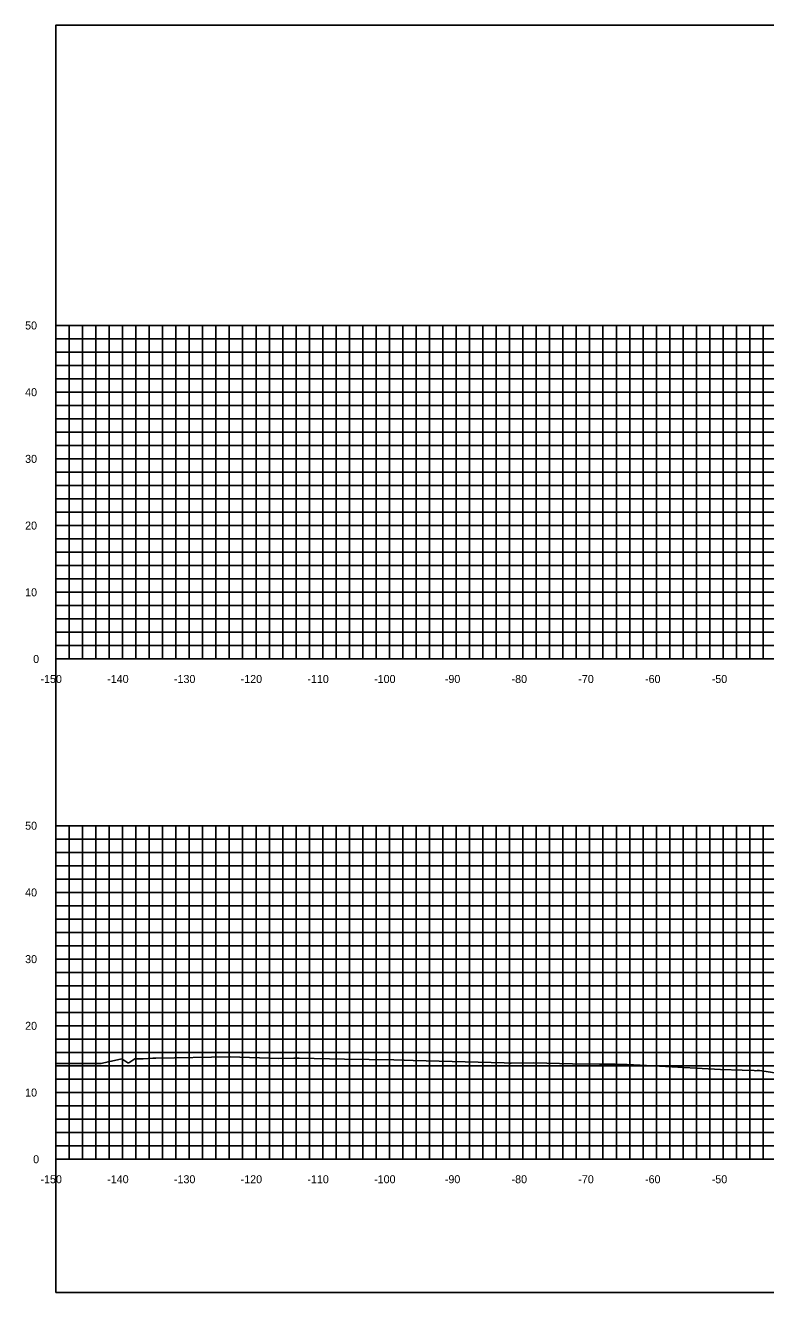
# Model space of a CAD drawing. Extents: x 1797714 to 1804825, y 249015 to 250269.
# Drawn here: x 1802449.6 to 1802560.5, y 249628.2 to 249818.2 of the extents above; entities that cross this region are included whole.
import ezdxf

# ---------------------------------------------------------------- set-up
doc = ezdxf.new("R2010")
doc.units = 0
for name, color, linetype in [('10', 7, 'Continuous'), ('31', 7, 'Continuous'), ('60', 7, 'Continuous'), ('Level 62', 7, 'Continuous'), ('M-ROADS', 7, 'Continuous')]:
    doc.layers.add(name, color=color, linetype=linetype)

msp = doc.modelspace()

# ---------------------------------------------------------------- linework, layer by layer
msp.add_lwpolyline([(1802454.16, 249628.17), (1802754.16, 249628.17), (1802754.16, 249818.17), (1802454.16, 249818.17)], close=True)
at = {"layer": '60'}
for p, q in [((1802454.1, 249773.17), (1802454.16, 249773.17)), ((1802454.16, 249723.17), (1802454.16, 249773.17)), ((1802454.1, 249763.17), (1802454.16, 249763.17)), ((1802454.1, 249753.17), (1802454.16, 249753.17)), ((1802454.1, 249743.17), (1802454.16, 249743.17)), ((1802454.1, 249733.17), (1802454.16, 249733.17)), ((1802454.1, 249723.17), (1802454.16, 249723.17)), ((1802454.16, 249723.17), (1802754.16, 249723.17)), ((1802454.16, 249723.11), (1802454.16, 249723.17)), ((1802464.16, 249723.11), (1802464.16, 249723.17)), ((1802474.16, 249723.11), (1802474.16, 249723.17)), ((1802484.16, 249723.11), (1802484.16, 249723.17)), ((1802494.16, 249723.11), (1802494.16, 249723.17)), ((1802504.16, 249723.11), (1802504.16, 249723.17)), ((1802514.16, 249723.11), (1802514.16, 249723.17)), ((1802524.16, 249723.11), (1802524.16, 249723.17)), ((1802534.16, 249723.11), (1802534.16, 249723.17)), ((1802544.16, 249723.11), (1802544.16, 249723.17)), ((1802554.16, 249723.11), (1802554.16, 249723.17)), ((1802454.1, 249698.17), (1802454.16, 249698.17)), ((1802454.16, 249648.17), (1802454.16, 249698.17)), ((1802454.1, 249688.17), (1802454.16, 249688.17)), ((1802454.1, 249678.17), (1802454.16, 249678.17)), ((1802454.1, 249668.17), (1802454.16, 249668.17)), ((1802454.1, 249658.17), (1802454.16, 249658.17)), ((1802454.1, 249648.17), (1802454.16, 249648.17)), ((1802454.16, 249648.17), (1802754.16, 249648.17)), ((1802454.16, 249648.11), (1802454.16, 249648.17)), ((1802464.16, 249648.11), (1802464.16, 249648.17)), ((1802474.16, 249648.11), (1802474.16, 249648.17)), ((1802484.16, 249648.11), (1802484.16, 249648.17)), ((1802494.16, 249648.11), (1802494.16, 249648.17)), ((1802504.16, 249648.11), (1802504.16, 249648.17)), ((1802514.16, 249648.11), (1802514.16, 249648.17)), ((1802524.16, 249648.11), (1802524.16, 249648.17)), ((1802534.16, 249648.11), (1802534.16, 249648.17)), ((1802544.16, 249648.11), (1802544.16, 249648.17)), ((1802554.16, 249648.11), (1802554.16, 249648.17))]:
    msp.add_line(p, q, dxfattribs=at)
at = {"layer": 'Level 62'}
for p, q in [((1802454.16, 249773.17), (1802754.16, 249773.17)), ((1802454.16, 249723.17), (1802454.16, 249773.17)), ((1802456.16, 249723.17), (1802456.16, 249773.17)), ((1802458.16, 249723.17), (1802458.16, 249773.17)), ((1802460.16, 249723.17), (1802460.16, 249773.17)), ((1802462.16, 249723.17), (1802462.16, 249773.17)), ((1802464.16, 249723.17), (1802464.16, 249773.17)), ((1802466.16, 249723.17), (1802466.16, 249773.17)), ((1802468.16, 249723.17), (1802468.16, 249773.17)), ((1802470.16, 249723.17), (1802470.16, 249773.17)), ((1802472.16, 249723.17), (1802472.16, 249773.17)), ((1802474.16, 249723.17), (1802474.16, 249773.17)), ((1802476.16, 249723.17), (1802476.16, 249773.17)), ((1802478.16, 249723.17), (1802478.16, 249773.17)), ((1802480.16, 249723.17), (1802480.16, 249773.17)), ((1802482.16, 249723.17), (1802482.16, 249773.17)), ((1802484.16, 249723.17), (1802484.16, 249773.17)), ((1802486.16, 249723.17), (1802486.16, 249773.17)), ((1802488.16, 249723.17), (1802488.16, 249773.17)), ((1802490.16, 249723.17), (1802490.16, 249773.17)), ((1802492.16, 249723.17), (1802492.16, 249773.17)), ((1802494.16, 249723.17), (1802494.16, 249773.17)), ((1802496.16, 249723.17), (1802496.16, 249773.17)), ((1802498.16, 249723.17), (1802498.16, 249773.17)), ((1802500.16, 249723.17), (1802500.16, 249773.17)), ((1802502.16, 249723.17), (1802502.16, 249773.17)), ((1802504.16, 249723.17), (1802504.16, 249773.17)), ((1802506.16, 249723.17), (1802506.16, 249773.17)), ((1802508.16, 249723.17), (1802508.16, 249773.17)), ((1802510.16, 249723.17), (1802510.16, 249773.17)), ((1802512.16, 249723.17), (1802512.16, 249773.17)), ((1802514.16, 249723.17), (1802514.16, 249773.17)), ((1802516.16, 249723.17), (1802516.16, 249773.17)), ((1802518.16, 249723.17), (1802518.16, 249773.17)), ((1802520.16, 249723.17), (1802520.16, 249773.17)), ((1802522.16, 249723.17), (1802522.16, 249773.17)), ((1802524.16, 249723.17), (1802524.16, 249773.17)), ((1802526.16, 249723.17), (1802526.16, 249773.17)), ((1802528.16, 249723.17), (1802528.16, 249773.17)), ((1802530.16, 249723.17), (1802530.16, 249773.17)), ((1802532.16, 249723.17), (1802532.16, 249773.17)), ((1802534.16, 249723.17), (1802534.16, 249773.17)), ((1802536.16, 249723.17), (1802536.16, 249773.17)), ((1802538.16, 249723.17), (1802538.16, 249773.17)), ((1802540.16, 249723.17), (1802540.16, 249773.17)), ((1802542.16, 249723.17), (1802542.16, 249773.17)), ((1802544.16, 249723.17), (1802544.16, 249773.17)), ((1802546.16, 249723.17), (1802546.16, 249773.17)), ((1802548.16, 249723.17), (1802548.16, 249773.17)), ((1802550.16, 249723.17), (1802550.16, 249773.17)), ((1802552.16, 249723.17), (1802552.16, 249773.17)), ((1802554.16, 249723.17), (1802554.16, 249773.17)), ((1802556.16, 249723.17), (1802556.16, 249773.17)), ((1802558.16, 249723.17), (1802558.16, 249773.17)), ((1802560.16, 249723.17), (1802560.16, 249773.17)), ((1802454.16, 249771.17), (1802754.16, 249771.17)), ((1802454.16, 249769.17), (1802754.16, 249769.17)), ((1802454.16, 249767.17), (1802754.16, 249767.17)), ((1802454.16, 249765.17), (1802754.16, 249765.17)), ((1802454.16, 249763.17), (1802754.16, 249763.17)), ((1802454.16, 249761.17), (1802754.16, 249761.17)), ((1802454.16, 249759.17), (1802754.16, 249759.17)), ((1802454.16, 249757.17), (1802754.16, 249757.17)), ((1802454.16, 249755.17), (1802754.16, 249755.17)), ((1802454.16, 249753.17), (1802754.16, 249753.17)), ((1802454.16, 249751.17), (1802754.16, 249751.17)), ((1802454.16, 249749.17), (1802754.16, 249749.17)), ((1802454.16, 249747.17), (1802754.16, 249747.17)), ((1802454.16, 249745.17), (1802754.16, 249745.17)), ((1802454.16, 249743.17), (1802754.16, 249743.17)), ((1802454.16, 249741.17), (1802754.16, 249741.17)), ((1802454.16, 249739.17), (1802754.16, 249739.17)), ((1802454.16, 249737.17), (1802754.16, 249737.17)), ((1802454.16, 249735.17), (1802754.16, 249735.17)), ((1802454.16, 249733.17), (1802754.16, 249733.17)), ((1802454.16, 249731.17), (1802754.16, 249731.17)), ((1802454.16, 249729.17), (1802754.16, 249729.17)), ((1802454.16, 249727.17), (1802754.16, 249727.17)), ((1802454.16, 249725.17), (1802754.16, 249725.17)), ((1802454.16, 249723.17), (1802754.16, 249723.17)), ((1802454.16, 249698.17), (1802754.16, 249698.17)), ((1802454.16, 249648.17), (1802454.16, 249698.17)), ((1802456.16, 249648.17), (1802456.16, 249698.17)), ((1802458.16, 249648.17), (1802458.16, 249698.17)), ((1802460.16, 249648.17), (1802460.16, 249698.17)), ((1802462.16, 249648.17), (1802462.16, 249698.17)), ((1802464.16, 249648.17), (1802464.16, 249698.17)), ((1802466.16, 249648.17), (1802466.16, 249698.17)), ((1802468.16, 249648.17), (1802468.16, 249698.17)), ((1802470.16, 249648.17), (1802470.16, 249698.17)), ((1802472.16, 249648.17), (1802472.16, 249698.17)), ((1802474.16, 249648.17), (1802474.16, 249698.17)), ((1802476.16, 249648.17), (1802476.16, 249698.17)), ((1802478.16, 249648.17), (1802478.16, 249698.17)), ((1802480.16, 249648.17), (1802480.16, 249698.17)), ((1802482.16, 249648.17), (1802482.16, 249698.17)), ((1802484.16, 249648.17), (1802484.16, 249698.17)), ((1802486.16, 249648.17), (1802486.16, 249698.17)), ((1802488.16, 249648.17), (1802488.16, 249698.17)), ((1802490.16, 249648.17), (1802490.16, 249698.17)), ((1802492.16, 249648.17), (1802492.16, 249698.17)), ((1802494.16, 249648.17), (1802494.16, 249698.17)), ((1802496.16, 249648.17), (1802496.16, 249698.17)), ((1802498.16, 249648.17), (1802498.16, 249698.17)), ((1802500.16, 249648.17), (1802500.16, 249698.17)), ((1802502.16, 249648.17), (1802502.16, 249698.17)), ((1802504.16, 249648.17), (1802504.16, 249698.17)), ((1802506.16, 249648.17), (1802506.16, 249698.17)), ((1802508.16, 249648.17), (1802508.16, 249698.17)), ((1802510.16, 249648.17), (1802510.16, 249698.17)), ((1802512.16, 249648.17), (1802512.16, 249698.17)), ((1802514.16, 249648.17), (1802514.16, 249698.17)), ((1802516.16, 249648.17), (1802516.16, 249698.17)), ((1802518.16, 249648.17), (1802518.16, 249698.17)), ((1802520.16, 249648.17), (1802520.16, 249698.17)), ((1802522.16, 249648.17), (1802522.16, 249698.17)), ((1802524.16, 249648.17), (1802524.16, 249698.17)), ((1802526.16, 249648.17), (1802526.16, 249698.17)), ((1802528.16, 249648.17), (1802528.16, 249698.17)), ((1802530.16, 249648.17), (1802530.16, 249698.17)), ((1802532.16, 249648.17), (1802532.16, 249698.17)), ((1802534.16, 249648.17), (1802534.16, 249698.17)), ((1802536.16, 249648.17), (1802536.16, 249698.17)), ((1802538.16, 249648.17), (1802538.16, 249698.17)), ((1802540.16, 249648.17), (1802540.16, 249698.17)), ((1802542.16, 249648.17), (1802542.16, 249698.17)), ((1802544.16, 249648.17), (1802544.16, 249698.17)), ((1802546.16, 249648.17), (1802546.16, 249698.17)), ((1802548.16, 249648.17), (1802548.16, 249698.17)), ((1802550.16, 249648.17), (1802550.16, 249698.17)), ((1802552.16, 249648.17), (1802552.16, 249698.17)), ((1802554.16, 249648.17), (1802554.16, 249698.17)), ((1802556.16, 249648.17), (1802556.16, 249698.17)), ((1802558.16, 249648.17), (1802558.16, 249698.17)), ((1802560.16, 249648.17), (1802560.16, 249698.17)), ((1802454.16, 249696.17), (1802754.16, 249696.17)), ((1802454.16, 249694.17), (1802754.16, 249694.17)), ((1802454.16, 249692.17), (1802754.16, 249692.17)), ((1802454.16, 249690.17), (1802754.16, 249690.17)), ((1802454.16, 249688.17), (1802754.16, 249688.17)), ((1802454.16, 249686.17), (1802754.16, 249686.17)), ((1802454.16, 249684.17), (1802754.16, 249684.17)), ((1802454.16, 249682.17), (1802754.16, 249682.17)), ((1802454.16, 249680.17), (1802754.16, 249680.17)), ((1802454.16, 249678.17), (1802754.16, 249678.17)), ((1802454.16, 249676.17), (1802754.16, 249676.17)), ((1802454.16, 249674.17), (1802754.16, 249674.17)), ((1802454.16, 249672.17), (1802754.16, 249672.17)), ((1802454.16, 249670.17), (1802754.16, 249670.17)), ((1802454.16, 249668.17), (1802754.16, 249668.17)), ((1802454.16, 249666.17), (1802754.16, 249666.17)), ((1802454.16, 249664.17), (1802754.16, 249664.17)), ((1802454.16, 249662.17), (1802754.16, 249662.17)), ((1802454.16, 249660.17), (1802754.16, 249660.17)), ((1802454.16, 249658.17), (1802754.16, 249658.17)), ((1802454.16, 249656.17), (1802754.16, 249656.17)), ((1802454.16, 249654.17), (1802754.16, 249654.17)), ((1802454.16, 249652.17), (1802754.16, 249652.17)), ((1802454.16, 249650.17), (1802754.16, 249650.17)), ((1802454.16, 249648.17), (1802754.16, 249648.17))]:
    msp.add_line(p, q, dxfattribs=at)
at = {"layer": 'M-ROADS'}
msp.add_lwpolyline([(1802454.16, 249662.51), (1802457.28, 249662.51), (1802457.65, 249662.51), (1802458.07, 249662.51), (1802459.05, 249662.51), (1802459.89, 249662.51), (1802460.37, 249662.51), (1802460.94, 249662.51), (1802461.98, 249662.79), (1802462.5, 249662.86), (1802464.03, 249663.21), (1802464.94, 249662.61), (1802465.09, 249662.6), (1802465.98, 249663.23), (1802466.73, 249663.2), (1802467.25, 249663.23), (1802468.71, 249663.33), (1802469.13, 249663.3), (1802480.28, 249663.51), (1802487.6, 249663.25), (1802489.84, 249663.3), (1802490.65, 249663.31), (1802497.44, 249663.19), (1802504.81, 249663.09), (1802506.37, 249663.03), (1802507.69, 249662.98), (1802521.36, 249662.61), (1802522.25, 249662.58), (1802522.38, 249662.58), (1802525.82, 249662.61), (1802531.61, 249662.46), (1802535.62, 249662.41), (1802536.97, 249662.41), (1802537.98, 249662.41), (1802539.79, 249662.35), (1802544.61, 249662.1), (1802553.79, 249661.61), (1802557, 249661.53), (1802558.82, 249661.45), (1802559, 249661.44), (1802559.25, 249661.47), (1802559.63, 249661.47), (1802564.86, 249660.66)], dxfattribs=at)

# ---------------------------------------------------------------- texts
at = {"layer": '10'}
for s, p in [('-150', (1802451.86, 249719.57)), ('-140', (1802461.86, 249719.57)), ('-130', (1802471.86, 249719.57)), ('-120', (1802481.86, 249719.57)), ('-110', (1802491.86, 249719.57)), ('-100', (1802501.86, 249719.57)), ('-90', (1802512.46, 249719.57)), ('-80', (1802522.46, 249719.57)), ('-70', (1802532.46, 249719.57)), ('-60', (1802542.46, 249719.57)), ('-50', (1802552.46, 249719.57)), ('-150', (1802451.86, 249644.57)), ('-140', (1802461.86, 249644.57)), ('-130', (1802471.86, 249644.57)), ('-120', (1802481.86, 249644.57)), ('-110', (1802491.86, 249644.57)), ('-100', (1802501.86, 249644.57)), ('-90', (1802512.46, 249644.57)), ('-80', (1802522.46, 249644.57)), ('-70', (1802532.46, 249644.57)), ('-60', (1802542.46, 249644.57)), ('-50', (1802552.46, 249644.57))]:
    msp.add_text(s, height=1.2, dxfattribs=at).set_placement(p)
at = {"layer": '31'}
for s, p in [('50', (1802449.56, 249772.57)), ('40', (1802449.56, 249762.57)), ('30', (1802449.56, 249752.57)), ('20', (1802449.56, 249742.57)), ('10', (1802449.56, 249732.57)), ('0', (1802450.76, 249722.57)), ('50', (1802449.56, 249697.57)), ('40', (1802449.56, 249687.57)), ('30', (1802449.56, 249677.57)), ('20', (1802449.56, 249667.57)), ('10', (1802449.56, 249657.57)), ('0', (1802450.76, 249647.57))]:
    msp.add_text(s, height=1.2, dxfattribs=at).set_placement(p)
at = {"layer": '60'}
for p in [(1802454.16, 249723.17), (1802454.16, 249648.17)]:
    msp.add_text('-', height=0.0001, dxfattribs=at).set_placement(p)

doc.saveas('drawing.dxf')
